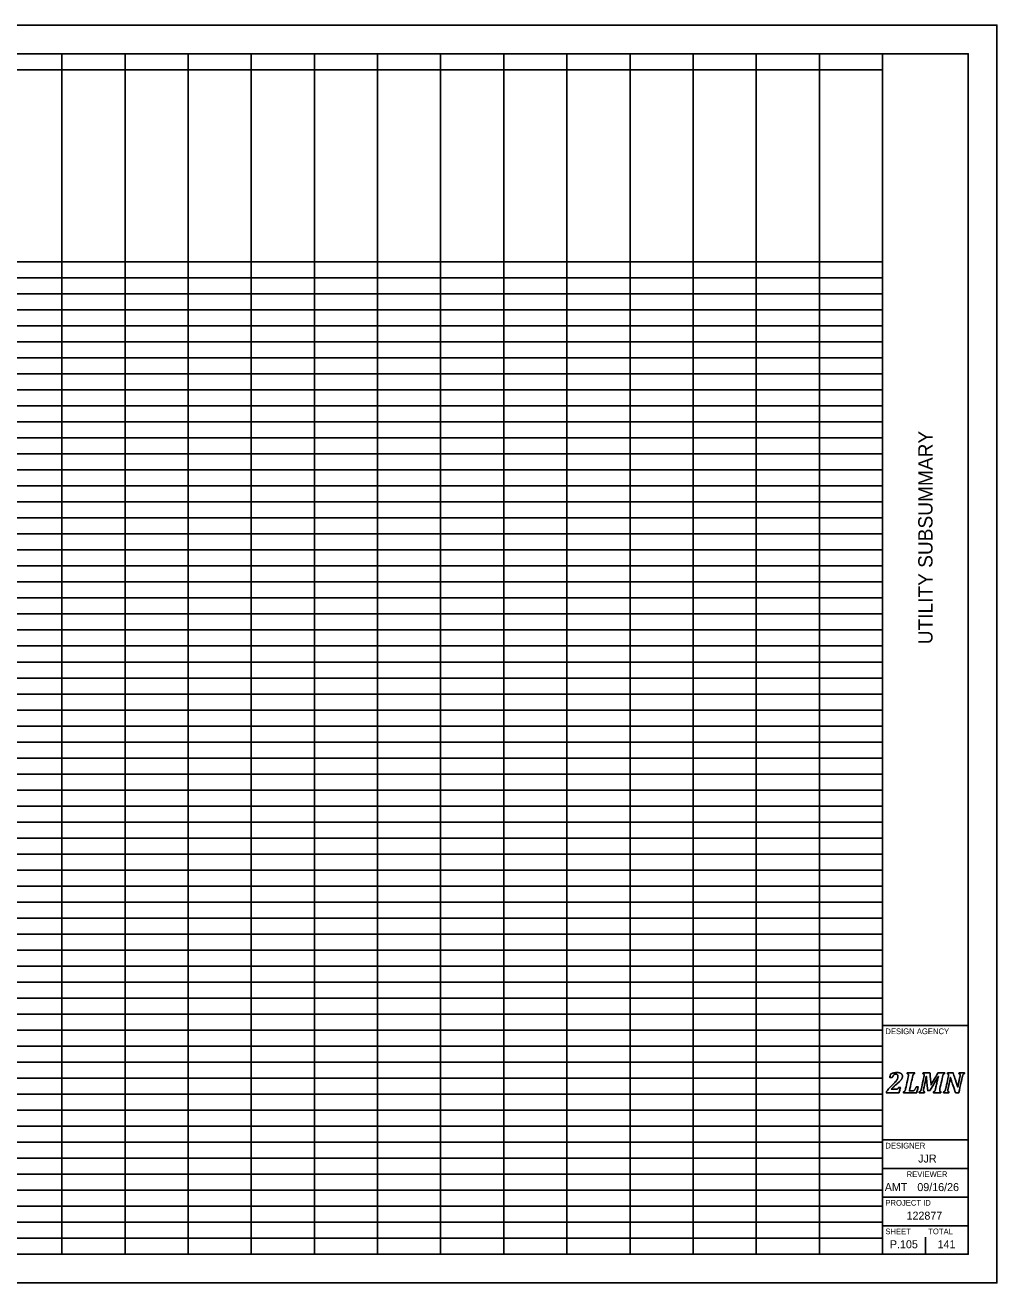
# Model space of a CAD drawing. Extents: x 0 to 34, y 0 to 22.
# Drawn here: x 17 to 34, y 0 to 22 of the extents above; entities that cross this region are included whole.
import ezdxf

# ---------------------------------------------------------------- set-up
doc = ezdxf.new("R2010")
doc.units = 0
for name, color, linetype in [('SH_Border', 7, 'Continuous'), ('SH_Cut_Line', 7, 'Continuous'), ('SH_Data', 7, 'Continuous'), ('SH_Text', 7, 'Continuous')]:
    doc.layers.add(name, color=color, linetype=linetype)

msp = doc.modelspace()

# ---------------------------------------------------------------- linework, layer by layer
at = {"layer": 'SH_Border'}
for p, q in [((32, 0.5), (32, 21.5)), ((32, 4.5), (33.5, 4.5)), ((32, 2.5), (33.5, 2.5)), ((32, 2), (33.5, 2)), ((32, 1.5), (33.5, 1.5)), ((32, 1), (33.5, 1))]:
    msp.add_line(p, q, dxfattribs=at)
msp.add_lwpolyline([(1.5, 21.5), (33.5, 21.5), (33.5, 0.5), (1.5, 0.5)], close=True, dxfattribs=at)
at = {"layer": 'SH_Cut_Line'}
msp.add_lwpolyline([(0, 0), (34, 0), (34, 22), (0, 22)], close=True, dxfattribs=at)
at = {"layer": 'SH_Data'}
for p, q in [((32.75, 3.5), (32.75, 3.5)), ((32.375, 0.675), (32.375, 0.675)), ((32.75, 0.5), (32.75, 0.8))]:
    msp.add_line(p, q, dxfattribs=at)
for points in [[(32.237, 3.388), (32.246, 3.388), (32.253, 3.389), (32.258, 3.39), (32.263, 3.392), (32.267, 3.394), (32.27, 3.397), (32.273, 3.401), (32.277, 3.408), (32.281, 3.417), (32.281, 3.417), (32.312, 3.417), (32.312, 3.417), (32.312, 3.417), (32.29, 3.326), (32.29, 3.326), (32.29, 3.326), (32.066, 3.326), (32.066, 3.326), (32.066, 3.326), (32.069, 3.343), (32.069, 3.343), (32.078, 3.358), (32.091, 3.375), (32.106, 3.394), (32.122, 3.412), (32.144, 3.435), (32.172, 3.462), (32.197, 3.486), (32.217, 3.506), (32.23, 3.521), (32.243, 3.537), (32.253, 3.551), (32.259, 3.566), (32.266, 3.58), (32.269, 3.595), (32.269, 3.61), (32.269, 3.622), (32.266, 3.632), (32.26, 3.64), (32.253, 3.647), (32.245, 3.65), (32.234, 3.65), (32.22, 3.65), (32.208, 3.646), (32.198, 3.636), (32.188, 3.627), (32.18, 3.613), (32.172, 3.593), (32.172, 3.593), (32.126, 3.593), (32.126, 3.593), (32.126, 3.593), (32.14, 3.654), (32.14, 3.654), (32.166, 3.663), (32.188, 3.669), (32.205, 3.673), (32.223, 3.676), (32.24, 3.678), (32.258, 3.678), (32.278, 3.678), (32.295, 3.675), (32.309, 3.669), (32.322, 3.664), (32.332, 3.656), (32.339, 3.646), (32.345, 3.637), (32.348, 3.626), (32.348, 3.613), (32.348, 3.602), (32.346, 3.591), (32.342, 3.581), (32.339, 3.571), (32.333, 3.56), (32.324, 3.549), (32.315, 3.539), (32.304, 3.526), (32.289, 3.513), (32.275, 3.499), (32.254, 3.482), (32.228, 3.46), (32.216, 3.45), (32.202, 3.438), (32.188, 3.425), (32.174, 3.412), (32.162, 3.4), (32.154, 3.391), (32.154, 3.391), (32.153, 3.388), (32.153, 3.388), (32.153, 3.388), (32.237, 3.388), (32.237, 3.388)], [(32.237, 3.388), (32.237, 3.388), (32.153, 3.388), (32.153, 3.388), (32.153, 3.388), (32.154, 3.391), (32.154, 3.391), (32.162, 3.4), (32.174, 3.412), (32.188, 3.425), (32.202, 3.438), (32.216, 3.45), (32.228, 3.46), (32.254, 3.482), (32.275, 3.499), (32.289, 3.513), (32.304, 3.526), (32.315, 3.539), (32.324, 3.549), (32.333, 3.56), (32.339, 3.571), (32.342, 3.581), (32.346, 3.591), (32.348, 3.602), (32.348, 3.613), (32.348, 3.626), (32.345, 3.637), (32.339, 3.646), (32.332, 3.656), (32.322, 3.664), (32.309, 3.669), (32.295, 3.675), (32.278, 3.678), (32.258, 3.678), (32.24, 3.678), (32.223, 3.676), (32.205, 3.673), (32.188, 3.669), (32.166, 3.663), (32.14, 3.654), (32.14, 3.654), (32.126, 3.593), (32.126, 3.593), (32.126, 3.593), (32.172, 3.593), (32.172, 3.593), (32.18, 3.613), (32.188, 3.627), (32.198, 3.636), (32.208, 3.646), (32.22, 3.65), (32.234, 3.65), (32.245, 3.65), (32.253, 3.647), (32.26, 3.64), (32.266, 3.632), (32.269, 3.622), (32.269, 3.61), (32.269, 3.595), (32.266, 3.58), (32.259, 3.566), (32.253, 3.551), (32.243, 3.537), (32.23, 3.521), (32.217, 3.506), (32.197, 3.486), (32.172, 3.462), (32.144, 3.435), (32.122, 3.412), (32.106, 3.394), (32.091, 3.375), (32.078, 3.358), (32.069, 3.343), (32.069, 3.343), (32.066, 3.326), (32.066, 3.326), (32.066, 3.326), (32.29, 3.326), (32.29, 3.326), (32.29, 3.326), (32.312, 3.417), (32.312, 3.417), (32.312, 3.417), (32.281, 3.417), (32.281, 3.417), (32.277, 3.408), (32.273, 3.401), (32.27, 3.397), (32.267, 3.394), (32.263, 3.392), (32.258, 3.39), (32.253, 3.389), (32.246, 3.388), (32.237, 3.388)], [(32.518, 3.356), (32.527, 3.356), (32.533, 3.357), (32.538, 3.358), (32.542, 3.36), (32.546, 3.362), (32.55, 3.365), (32.554, 3.368), (32.558, 3.372), (32.562, 3.377), (32.567, 3.382), (32.571, 3.388), (32.576, 3.397), (32.58, 3.405), (32.585, 3.415), (32.589, 3.427), (32.589, 3.427), (32.624, 3.427), (32.624, 3.427), (32.624, 3.427), (32.598, 3.326), (32.598, 3.326), (32.598, 3.326), (32.365, 3.326), (32.365, 3.326), (32.365, 3.326), (32.369, 3.343), (32.369, 3.343), (32.376, 3.345), (32.381, 3.348), (32.385, 3.351), (32.389, 3.355), (32.392, 3.36), (32.395, 3.366), (32.398, 3.373), (32.4, 3.382), (32.403, 3.395), (32.403, 3.395), (32.449, 3.605), (32.449, 3.605), (32.452, 3.615), (32.453, 3.625), (32.453, 3.635), (32.453, 3.642), (32.451, 3.647), (32.448, 3.651), (32.444, 3.654), (32.439, 3.656), (32.432, 3.657), (32.432, 3.657), (32.435, 3.674), (32.435, 3.674), (32.435, 3.674), (32.563, 3.674), (32.563, 3.674), (32.563, 3.674), (32.559, 3.657), (32.559, 3.657), (32.552, 3.655), (32.547, 3.652), (32.543, 3.649), (32.539, 3.645), (32.536, 3.64), (32.533, 3.634), (32.531, 3.627), (32.528, 3.618), (32.525, 3.605), (32.525, 3.605), (32.47, 3.356), (32.47, 3.356), (32.47, 3.356), (32.518, 3.356), (32.518, 3.356)], [(32.518, 3.356), (32.518, 3.356), (32.47, 3.356), (32.47, 3.356), (32.47, 3.356), (32.525, 3.605), (32.525, 3.605), (32.528, 3.618), (32.531, 3.627), (32.533, 3.634), (32.536, 3.64), (32.539, 3.645), (32.543, 3.649), (32.547, 3.652), (32.552, 3.655), (32.559, 3.657), (32.559, 3.657), (32.563, 3.674), (32.563, 3.674), (32.563, 3.674), (32.435, 3.674), (32.435, 3.674), (32.435, 3.674), (32.432, 3.657), (32.432, 3.657), (32.439, 3.656), (32.444, 3.654), (32.448, 3.651), (32.451, 3.647), (32.453, 3.642), (32.453, 3.635), (32.453, 3.625), (32.452, 3.615), (32.449, 3.605), (32.449, 3.605), (32.403, 3.395), (32.403, 3.395), (32.4, 3.382), (32.398, 3.373), (32.395, 3.366), (32.392, 3.36), (32.389, 3.355), (32.385, 3.351), (32.381, 3.348), (32.376, 3.345), (32.369, 3.343), (32.369, 3.343), (32.365, 3.326), (32.365, 3.326), (32.365, 3.326), (32.598, 3.326), (32.598, 3.326), (32.598, 3.326), (32.624, 3.427), (32.624, 3.427), (32.624, 3.427), (32.589, 3.427), (32.589, 3.427), (32.585, 3.415), (32.58, 3.405), (32.576, 3.397), (32.571, 3.388), (32.567, 3.382), (32.562, 3.377), (32.558, 3.372), (32.554, 3.368), (32.55, 3.365), (32.546, 3.362), (32.542, 3.36), (32.538, 3.358), (32.533, 3.357), (32.527, 3.356), (32.518, 3.356)], [(32.829, 3.674), (32.829, 3.674), (32.849, 3.461), (32.849, 3.461), (32.849, 3.461), (32.969, 3.674), (32.969, 3.674), (32.969, 3.674), (33.087, 3.674), (33.087, 3.674), (33.087, 3.674), (33.084, 3.657), (33.084, 3.657), (33.077, 3.655), (33.071, 3.652), (33.067, 3.649), (33.064, 3.645), (33.06, 3.64), (33.058, 3.634), (33.055, 3.627), (33.052, 3.618), (33.05, 3.605), (33.05, 3.605), (33.003, 3.395), (33.003, 3.395), (33.002, 3.39), (33.002, 3.387), (33.001, 3.384), (33.001, 3.382), (33.001, 3.379), (33, 3.376), (33, 3.373), (33, 3.369), (33, 3.365), (33, 3.358), (33.002, 3.353), (33.005, 3.349), (33.008, 3.346), (33.014, 3.344), (33.021, 3.343), (33.021, 3.343), (33.018, 3.326), (33.018, 3.326), (33.018, 3.326), (32.89, 3.326), (32.89, 3.326), (32.89, 3.326), (32.893, 3.343), (32.893, 3.343), (32.9, 3.345), (32.906, 3.348), (32.91, 3.351), (32.914, 3.355), (32.917, 3.36), (32.919, 3.366), (32.922, 3.373), (32.925, 3.382), (32.928, 3.395), (32.928, 3.395), (32.951, 3.502), (32.951, 3.502), (32.954, 3.513), (32.957, 3.529), (32.962, 3.548), (32.967, 3.568), (32.972, 3.588), (32.978, 3.609), (32.978, 3.609), (32.973, 3.609), (32.973, 3.609), (32.965, 3.594), (32.957, 3.579), (32.948, 3.563), (32.948, 3.563), (32.833, 3.364), (32.833, 3.364), (32.833, 3.364), (32.792, 3.364), (32.792, 3.364), (32.792, 3.364), (32.775, 3.518), (32.775, 3.518), (32.773, 3.537), (32.772, 3.554), (32.77, 3.569), (32.769, 3.583), (32.768, 3.597), (32.768, 3.611), (32.768, 3.611), (32.764, 3.611), (32.764, 3.611), (32.761, 3.596), (32.758, 3.578), (32.755, 3.558), (32.751, 3.538), (32.747, 3.521), (32.744, 3.507), (32.744, 3.507), (32.72, 3.395), (32.72, 3.395), (32.719, 3.39), (32.718, 3.387), (32.718, 3.384), (32.717, 3.382), (32.717, 3.379), (32.717, 3.376), (32.717, 3.373), (32.716, 3.369), (32.716, 3.365), (32.716, 3.358), (32.718, 3.353), (32.721, 3.349), (32.725, 3.346), (32.73, 3.344), (32.738, 3.343), (32.738, 3.343), (32.734, 3.326), (32.734, 3.326), (32.734, 3.326), (32.641, 3.326), (32.641, 3.326), (32.641, 3.326), (32.644, 3.343), (32.644, 3.343), (32.651, 3.345), (32.657, 3.348), (32.661, 3.351), (32.665, 3.355), (32.668, 3.36), (32.67, 3.366), (32.673, 3.373), (32.676, 3.382), (32.679, 3.395), (32.679, 3.395), (32.725, 3.605), (32.725, 3.605), (32.727, 3.615), (32.728, 3.625), (32.728, 3.635), (32.728, 3.642), (32.727, 3.647), (32.723, 3.651), (32.72, 3.654), (32.715, 3.656), (32.707, 3.657), (32.707, 3.657), (32.711, 3.674), (32.711, 3.674), (32.711, 3.674), (32.829, 3.674), (32.829, 3.674)], [(32.829, 3.674), (32.829, 3.674), (32.711, 3.674), (32.711, 3.674), (32.711, 3.674), (32.707, 3.657), (32.707, 3.657), (32.715, 3.656), (32.72, 3.654), (32.723, 3.651), (32.727, 3.647), (32.728, 3.642), (32.728, 3.635), (32.728, 3.625), (32.727, 3.615), (32.725, 3.605), (32.725, 3.605), (32.679, 3.395), (32.679, 3.395), (32.676, 3.382), (32.673, 3.373), (32.67, 3.366), (32.668, 3.36), (32.665, 3.355), (32.661, 3.351), (32.657, 3.348), (32.651, 3.345), (32.644, 3.343), (32.644, 3.343), (32.641, 3.326), (32.641, 3.326), (32.641, 3.326), (32.734, 3.326), (32.734, 3.326), (32.734, 3.326), (32.738, 3.343), (32.738, 3.343), (32.73, 3.344), (32.725, 3.346), (32.721, 3.349), (32.718, 3.353), (32.716, 3.358), (32.716, 3.365), (32.716, 3.369), (32.717, 3.373), (32.717, 3.376), (32.717, 3.379), (32.717, 3.382), (32.718, 3.384), (32.718, 3.387), (32.719, 3.39), (32.72, 3.395), (32.72, 3.395), (32.744, 3.507), (32.744, 3.507), (32.747, 3.521), (32.751, 3.538), (32.755, 3.558), (32.758, 3.578), (32.761, 3.596), (32.764, 3.611), (32.764, 3.611), (32.768, 3.611), (32.768, 3.611), (32.768, 3.597), (32.769, 3.583), (32.77, 3.569), (32.772, 3.554), (32.773, 3.537), (32.775, 3.518), (32.775, 3.518), (32.792, 3.364), (32.792, 3.364), (32.792, 3.364), (32.833, 3.364), (32.833, 3.364), (32.833, 3.364), (32.948, 3.563), (32.948, 3.563), (32.957, 3.579), (32.965, 3.594), (32.973, 3.609), (32.973, 3.609), (32.978, 3.609), (32.978, 3.609), (32.972, 3.588), (32.967, 3.568), (32.962, 3.548), (32.957, 3.529), (32.954, 3.513), (32.951, 3.502), (32.951, 3.502), (32.928, 3.395), (32.928, 3.395), (32.925, 3.382), (32.922, 3.373), (32.919, 3.366), (32.917, 3.36), (32.914, 3.355), (32.91, 3.351), (32.906, 3.348), (32.9, 3.345), (32.893, 3.343), (32.893, 3.343), (32.89, 3.326), (32.89, 3.326), (32.89, 3.326), (33.018, 3.326), (33.018, 3.326), (33.018, 3.326), (33.021, 3.343), (33.021, 3.343), (33.014, 3.344), (33.008, 3.346), (33.005, 3.349), (33.002, 3.353), (33, 3.358), (33, 3.365), (33, 3.369), (33, 3.373), (33, 3.376), (33.001, 3.379), (33.001, 3.382), (33.001, 3.384), (33.002, 3.387), (33.002, 3.39), (33.003, 3.395), (33.003, 3.395), (33.05, 3.605), (33.05, 3.605), (33.052, 3.618), (33.055, 3.627), (33.058, 3.634), (33.06, 3.64), (33.064, 3.645), (33.067, 3.649), (33.071, 3.652), (33.077, 3.655), (33.084, 3.657), (33.084, 3.657), (33.087, 3.674), (33.087, 3.674), (33.087, 3.674), (32.969, 3.674), (32.969, 3.674), (32.969, 3.674), (32.849, 3.461), (32.849, 3.461), (32.849, 3.461), (32.829, 3.674), (32.829, 3.674)], [(33.137, 3.674), (33.137, 3.674), (33.234, 3.674), (33.234, 3.674), (33.234, 3.674), (33.283, 3.53), (33.283, 3.53), (33.296, 3.49), (33.307, 3.456), (33.315, 3.426), (33.315, 3.426), (33.318, 3.426), (33.318, 3.426), (33.323, 3.455), (33.329, 3.488), (33.337, 3.523), (33.337, 3.523), (33.355, 3.605), (33.355, 3.605), (33.357, 3.615), (33.358, 3.625), (33.358, 3.635), (33.358, 3.642), (33.357, 3.647), (33.353, 3.651), (33.35, 3.654), (33.345, 3.656), (33.337, 3.657), (33.337, 3.657), (33.341, 3.674), (33.341, 3.674), (33.341, 3.674), (33.434, 3.674), (33.434, 3.674), (33.434, 3.674), (33.431, 3.657), (33.431, 3.657), (33.424, 3.655), (33.418, 3.652), (33.414, 3.649), (33.41, 3.645), (33.407, 3.64), (33.405, 3.634), (33.402, 3.627), (33.399, 3.618), (33.396, 3.605), (33.396, 3.605), (33.335, 3.326), (33.335, 3.326), (33.335, 3.326), (33.277, 3.326), (33.277, 3.326), (33.277, 3.326), (33.216, 3.504), (33.216, 3.504), (33.211, 3.518), (33.207, 3.531), (33.204, 3.543), (33.2, 3.556), (33.195, 3.571), (33.19, 3.59), (33.19, 3.59), (33.186, 3.59), (33.186, 3.59), (33.185, 3.579), (33.182, 3.563), (33.179, 3.543), (33.175, 3.523), (33.17, 3.501), (33.165, 3.478), (33.165, 3.478), (33.147, 3.395), (33.147, 3.395), (33.146, 3.39), (33.145, 3.387), (33.145, 3.384), (33.144, 3.382), (33.144, 3.379), (33.144, 3.376), (33.143, 3.373), (33.143, 3.369), (33.143, 3.365), (33.143, 3.358), (33.145, 3.353), (33.148, 3.349), (33.152, 3.346), (33.157, 3.344), (33.164, 3.343), (33.164, 3.343), (33.161, 3.326), (33.161, 3.326), (33.161, 3.326), (33.067, 3.326), (33.067, 3.326), (33.067, 3.326), (33.071, 3.343), (33.071, 3.343), (33.078, 3.345), (33.083, 3.348), (33.087, 3.351), (33.091, 3.355), (33.094, 3.36), (33.097, 3.366), (33.1, 3.373), (33.102, 3.382), (33.105, 3.395), (33.105, 3.395), (33.151, 3.605), (33.151, 3.605), (33.154, 3.615), (33.155, 3.625), (33.155, 3.635), (33.155, 3.642), (33.153, 3.647), (33.15, 3.651), (33.146, 3.654), (33.141, 3.656), (33.134, 3.657), (33.134, 3.657), (33.137, 3.674), (33.137, 3.674)], [(33.137, 3.674), (33.137, 3.674), (33.134, 3.657), (33.134, 3.657), (33.141, 3.656), (33.146, 3.654), (33.15, 3.651), (33.153, 3.647), (33.155, 3.642), (33.155, 3.635), (33.155, 3.625), (33.154, 3.615), (33.151, 3.605), (33.151, 3.605), (33.105, 3.395), (33.105, 3.395), (33.102, 3.382), (33.1, 3.373), (33.097, 3.366), (33.094, 3.36), (33.091, 3.355), (33.087, 3.351), (33.083, 3.348), (33.078, 3.345), (33.071, 3.343), (33.071, 3.343), (33.067, 3.326), (33.067, 3.326), (33.067, 3.326), (33.161, 3.326), (33.161, 3.326), (33.161, 3.326), (33.164, 3.343), (33.164, 3.343), (33.157, 3.344), (33.152, 3.346), (33.148, 3.349), (33.145, 3.353), (33.143, 3.358), (33.143, 3.365), (33.143, 3.369), (33.143, 3.373), (33.144, 3.376), (33.144, 3.379), (33.144, 3.382), (33.145, 3.384), (33.145, 3.387), (33.146, 3.39), (33.147, 3.395), (33.147, 3.395), (33.165, 3.478), (33.165, 3.478), (33.17, 3.501), (33.175, 3.523), (33.179, 3.543), (33.182, 3.563), (33.185, 3.579), (33.186, 3.59), (33.186, 3.59), (33.19, 3.59), (33.19, 3.59), (33.195, 3.571), (33.2, 3.556), (33.204, 3.543), (33.207, 3.531), (33.211, 3.518), (33.216, 3.504), (33.216, 3.504), (33.277, 3.326), (33.277, 3.326), (33.277, 3.326), (33.335, 3.326), (33.335, 3.326), (33.335, 3.326), (33.396, 3.605), (33.396, 3.605), (33.399, 3.618), (33.402, 3.627), (33.405, 3.634), (33.407, 3.64), (33.41, 3.645), (33.414, 3.649), (33.418, 3.652), (33.424, 3.655), (33.431, 3.657), (33.431, 3.657), (33.434, 3.674), (33.434, 3.674), (33.434, 3.674), (33.341, 3.674), (33.341, 3.674), (33.341, 3.674), (33.337, 3.657), (33.337, 3.657), (33.345, 3.656), (33.35, 3.654), (33.353, 3.651), (33.357, 3.647), (33.358, 3.642), (33.358, 3.635), (33.358, 3.625), (33.357, 3.615), (33.355, 3.605), (33.355, 3.605), (33.337, 3.523), (33.337, 3.523), (33.329, 3.488), (33.323, 3.455), (33.318, 3.426), (33.318, 3.426), (33.315, 3.426), (33.315, 3.426), (33.307, 3.456), (33.296, 3.49), (33.283, 3.53), (33.283, 3.53), (33.234, 3.674), (33.234, 3.674), (33.234, 3.674), (33.137, 3.674), (33.137, 3.674)]]:
    msp.add_open_spline(points, degree=3, dxfattribs=at)
at = {"layer": 'SH_Text'}
for p, q in [((1.5, 21.5), (32, 21.5)), ((17.643, 21.5), (17.643, 0.5)), ((18.748, 21.5), (18.748, 0.5)), ((19.852, 21.5), (19.852, 0.5)), ((20.956, 21.5), (20.956, 0.5)), ((22.061, 21.5), (22.061, 0.5)), ((23.165, 21.5), (23.165, 0.5)), ((24.269, 21.5), (24.269, 0.5)), ((25.374, 21.5), (25.374, 0.5)), ((26.478, 21.5), (26.478, 0.5)), ((27.583, 21.5), (27.583, 0.5)), ((28.687, 21.5), (28.687, 0.5)), ((29.791, 21.5), (29.791, 0.5)), ((30.896, 21.5), (30.896, 0.5)), ((32, 21.5), (32, 0.5)), ((9.913, 21.22), (32, 21.22)), ((9.913, 17.86), (32, 17.86)), ((1.5, 17.58), (32, 17.58)), ((1.5, 17.3), (32, 17.3)), ((1.5, 17.02), (32, 17.02)), ((1.5, 16.74), (32, 16.74)), ((1.5, 16.46), (32, 16.46)), ((1.5, 16.18), (32, 16.18)), ((1.5, 15.9), (32, 15.9)), ((1.5, 15.62), (32, 15.62)), ((1.5, 15.34), (32, 15.34)), ((1.5, 15.06), (32, 15.06)), ((1.5, 14.78), (32, 14.78)), ((1.5, 14.5), (32, 14.5)), ((1.5, 14.22), (32, 14.22)), ((1.5, 13.94), (32, 13.94)), ((1.5, 13.66), (32, 13.66)), ((1.5, 13.38), (32, 13.38)), ((1.5, 13.1), (32, 13.1)), ((1.5, 12.82), (32, 12.82)), ((1.5, 12.54), (32, 12.54)), ((1.5, 12.26), (32, 12.26)), ((1.5, 11.98), (32, 11.98)), ((1.5, 11.7), (32, 11.7)), ((1.5, 11.42), (32, 11.42)), ((1.5, 11.14), (32, 11.14)), ((1.5, 10.86), (32, 10.86)), ((1.5, 10.58), (32, 10.58)), ((1.5, 10.3), (32, 10.3)), ((1.5, 10.02), (32, 10.02)), ((1.5, 9.74), (32, 9.74)), ((1.5, 9.46), (32, 9.46)), ((1.5, 9.18), (32, 9.18)), ((1.5, 8.9), (32, 8.9)), ((1.5, 8.62), (32, 8.62)), ((1.5, 8.34), (32, 8.34)), ((1.5, 8.06), (32, 8.06)), ((1.5, 7.78), (32, 7.78)), ((1.5, 7.5), (32, 7.5)), ((1.5, 7.22), (32, 7.22)), ((1.5, 6.94), (32, 6.94)), ((1.5, 6.66), (32, 6.66)), ((1.5, 6.38), (32, 6.38)), ((1.5, 6.1), (32, 6.1)), ((1.5, 5.82), (32, 5.82)), ((1.5, 5.54), (32, 5.54)), ((1.5, 5.26), (32, 5.26)), ((1.5, 4.98), (32, 4.98)), ((1.5, 4.7), (32, 4.7)), ((1.5, 4.42), (32, 4.42)), ((1.5, 4.14), (32, 4.14)), ((1.5, 3.86), (32, 3.86)), ((1.5, 3.58), (32, 3.58)), ((1.5, 3.3), (32, 3.3)), ((1.5, 3.02), (32, 3.02)), ((1.5, 2.74), (32, 2.74)), ((1.5, 2.46), (32, 2.46)), ((1.5, 2.18), (32, 2.18)), ((1.5, 1.9), (32, 1.9)), ((1.5, 1.62), (32, 1.62)), ((1.5, 1.34), (32, 1.34)), ((1.5, 1.06), (32, 1.06)), ((1.5, 0.78), (32, 0.78)), ((1.5, 0.5), (32, 0.5))]:
    msp.add_line(p, q, dxfattribs=at)

# ---------------------------------------------------------------- texts
at = {"layer": 'SH_Data'}
msp.add_text('UTILITY SUBSUMMARY', height=0.25, rotation=90, dxfattribs=at).set_placement((32.875, 11.17))
for s, height, p in [('DESIGN AGENCY', 0.1, (32.05, 4.35)), ('DESIGNER', 0.1, (32.05, 2.35)), ('JJR', 0.14, (32.624, 2.105)), ('REVIEWER', 0.1, (32.422, 1.85)), ('AMT', 0.14, (32.039, 1.605)), ('09/16/26', 0.14, (32.609, 1.605)), ('PROJECT ID', 0.1, (32.05, 1.35)), ('122877', 0.14, (32.42, 1.105)), ('SHEET', 0.1, (32.05, 0.85)), ('TOTAL', 0.1, (32.8, 0.85)), ('P.105', 0.14, (32.129, 0.605)), ('141', 0.14, (32.963, 0.605))]:
    msp.add_text(s, height=height, dxfattribs=at).set_placement(p)

doc.saveas('drawing.dxf')
